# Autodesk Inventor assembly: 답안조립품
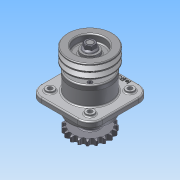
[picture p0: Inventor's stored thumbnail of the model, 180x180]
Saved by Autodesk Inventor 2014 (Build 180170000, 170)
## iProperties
Created: 2015-09
Part Number: 답안조립품
Document SubType Name: Assembly
Designer: study
Author: study
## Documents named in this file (11)
- C:\Users\study\Desktop\450909V1017\답안조립품.iam
- C:\Users\study\Desktop\450909V1017\1-본체.ipt
- C:\Users\study\Desktop\450909V1017\6-베어링 6206.ipt
- C:\Users\study\Desktop\450909V1017\2-커버.ipt
- C:\Users\study\Desktop\450909V1017\8-오일실 30x42.ipt
- C:\Users\study\Desktop\450909V1017\3-축.ipt
- C:\Users\study\Desktop\450909V1017\11-키 6x6.ipt
- C:\Users\study\Desktop\450909V1017\10-M6.ipt
- C:\Users\study\Desktop\450909V1017\5-체인 스프로킷.ipt
- C:\Users\study\Desktop\450909V1017\4-V벨트풀리.ipt
- C:\Users\study\Desktop\450909V1017\9-M16-너트.ipt
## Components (22 placed, 10 different names)
1. 1-본체:1
2. 6-베어링 6206:1
3. 6-베어링 6206:2
4. 2-커버:1
5. 8-8-오일실 30x42:1
6. 2-커버:2
7. 8-8-오일실 30x42:2
8. 3-축:1 — 각도:1, 각도:2
9. 11-키 6x6:1 — 각도:1, 각도:4
10. 11-키 6x6:2 — 각도:2, 각도:3
11. 5-체인 스프로킷:1 — 각도:3
12. 4-V벨트풀리:1 — 각도:4
13. 9-M16 너트:1
14. 9-M16 너트:2
15. 10-M6:1
16. 10-M6:3
17. 10-M6:4
18. 10-M6:5
19. 10-M6:2
20. 10-M6:6
21. 10-M6:7
22. 10-M6:8
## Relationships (4: Angle 4)
- 각도:1 [Angle]: 3-축:1 ↔ 11-키 6x6:1
- 각도:2 [Angle]: 3-축:1 ↔ 11-키 6x6:2
- 각도:3 [Angle]: 11-키 6x6:2 ↔ 5-체인 스프로킷:1
- 각도:4 [Angle]: 11-키 6x6:1 ↔ 4-V벨트풀리:1
